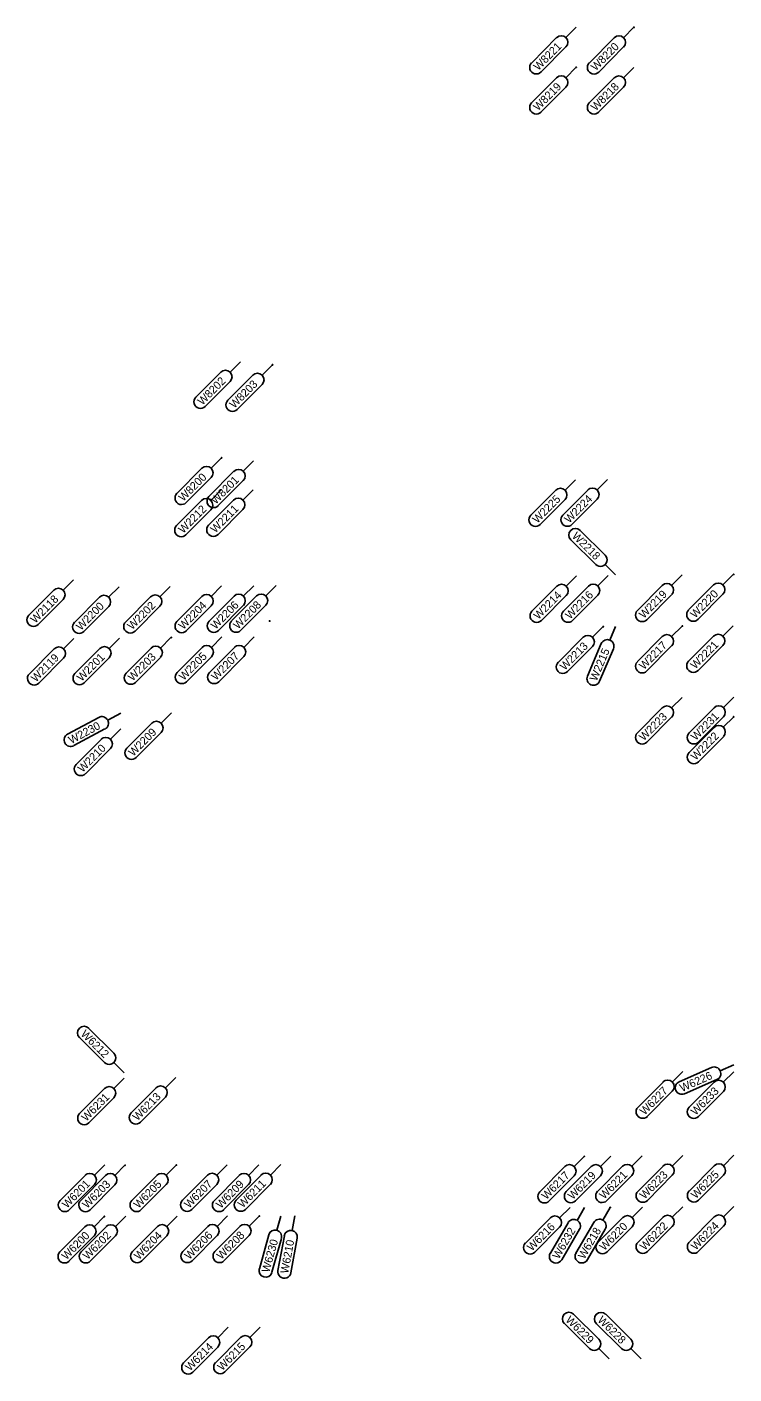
# Model space of a CAD drawing. Extents: x 12479652 to 12487250, y 9842710 to 9846560.
# Drawn here: x 12483645.7 to 12483756, y 9842728.2 to 9842938.7 of the extents above; entities that cross this region are included whole.
import ezdxf

# ---------------------------------------------------------------- set-up
doc = ezdxf.new("R2010")
doc.units = 0
doc.layers.add('_CIVIL_CONSTRUCTION', color=7, linetype='Continuous')
doc.layers.add('TextAlignmentLrg', color=7, linetype='Continuous')

msp = doc.modelspace()

# ---------------------------------------------------------------- linework, layer by layer
at = {"layer": '_CIVIL_CONSTRUCTION'}
for p, q in [((12483731.42, 9842938.62), (12483729.8, 9842936.99)), ((12483740.42, 9842938.61), (12483738.8, 9842936.98)), ((12483724.46, 9842933.07), (12483728.34, 9842936.99)), ((12483729.8, 9842935.54), (12483725.91, 9842931.63)), ((12483733.46, 9842933.06), (12483737.34, 9842936.98)), ((12483738.8, 9842935.53), (12483734.91, 9842931.62)), ((12483731.41, 9842932.36), (12483729.79, 9842930.73)), ((12483740.41, 9842932.35), (12483738.79, 9842930.72)), ((12483724.45, 9842926.81), (12483728.34, 9842930.72)), ((12483729.79, 9842929.27), (12483725.9, 9842925.36)), ((12483733.45, 9842926.8), (12483737.34, 9842930.71)), ((12483738.79, 9842929.27), (12483734.9, 9842925.35)), ((12483672.04, 9842880.81), (12483675.93, 9842884.73)), ((12483679, 9842886.36), (12483677.38, 9842884.73)), ((12483684, 9842885.88), (12483682.38, 9842884.25)), ((12483677.38, 9842883.28), (12483673.49, 9842879.37)), ((12483677.04, 9842880.34), (12483680.93, 9842884.25)), ((12483682.38, 9842882.8), (12483678.49, 9842878.89)), ((12483676.06, 9842871.35), (12483674.43, 9842869.72)), ((12483681.06, 9842870.87), (12483679.44, 9842869.24)), ((12483669.09, 9842865.8), (12483672.98, 9842869.71)), ((12483674.44, 9842868.27), (12483670.55, 9842864.35)), ((12483674.09, 9842865.32), (12483677.98, 9842869.24)), ((12483679.44, 9842867.79), (12483675.55, 9842863.88)), ((12483731.28, 9842867.92), (12483729.66, 9842866.29)), ((12483736.28, 9842867.96), (12483734.66, 9842866.33)), ((12483676.01, 9842866.33), (12483674.38, 9842864.7)), ((12483681.01, 9842866.37), (12483679.38, 9842864.74)), ((12483724.32, 9842862.37), (12483728.21, 9842866.28)), ((12483729.32, 9842862.41), (12483733.21, 9842866.32)), ((12483669.04, 9842860.78), (12483672.93, 9842864.7)), ((12483674.04, 9842860.83), (12483677.93, 9842864.74)), ((12483729.66, 9842864.84), (12483725.77, 9842860.92)), ((12483734.66, 9842864.88), (12483730.77, 9842860.97)), ((12483674.39, 9842863.25), (12483670.5, 9842859.34)), ((12483679.39, 9842863.29), (12483675.5, 9842859.38)), ((12483732, 9842860.02), (12483735.91, 9842856.13)), ((12483734.46, 9842854.67), (12483730.55, 9842858.56)), ((12483737.55, 9842853.05), (12483735.92, 9842854.68)), ((12483747.92, 9842853.06), (12483746.29, 9842851.43)), ((12483755.92, 9842853.12), (12483754.29, 9842851.49)), ((12483652.95, 9842852.31), (12483651.32, 9842850.67)), ((12483660.05, 9842851.2), (12483658.43, 9842849.57)), ((12483668.05, 9842851.27), (12483666.43, 9842849.64)), ((12483676.06, 9842851.33), (12483674.44, 9842849.7)), ((12483681.07, 9842851.37), (12483679.45, 9842849.74)), ((12483684.58, 9842851.4), (12483682.96, 9842849.77)), ((12483724.5, 9842847.37), (12483728.39, 9842851.28)), ((12483729.43, 9842847.41), (12483733.32, 9842851.32)), ((12483731.46, 9842852.92), (12483729.84, 9842851.29)), ((12483736.39, 9842852.96), (12483734.77, 9842851.33)), ((12483740.95, 9842847.51), (12483744.84, 9842851.42)), ((12483748.95, 9842847.58), (12483752.84, 9842851.49)), ((12483645.98, 9842846.76), (12483649.87, 9842850.67)), ((12483651.33, 9842849.22), (12483647.44, 9842845.31)), ((12483653.09, 9842845.65), (12483656.98, 9842849.56)), ((12483661.09, 9842845.72), (12483664.98, 9842849.63)), ((12483669.1, 9842845.78), (12483672.99, 9842849.7)), ((12483674.11, 9842845.83), (12483678, 9842849.74)), ((12483677.62, 9842845.86), (12483681.51, 9842849.77)), ((12483729.85, 9842849.84), (12483725.96, 9842845.92)), ((12483734.77, 9842849.88), (12483730.88, 9842845.97)), ((12483746.3, 9842849.97), (12483742.41, 9842846.06)), ((12483754.3, 9842850.04), (12483750.41, 9842846.13)), ((12483658.44, 9842848.12), (12483654.55, 9842844.2)), ((12483666.44, 9842848.18), (12483662.55, 9842844.27)), ((12483674.44, 9842848.25), (12483670.55, 9842844.34)), ((12483679.45, 9842848.29), (12483675.57, 9842844.38)), ((12483682.96, 9842848.32), (12483679.07, 9842844.41)), ((12483735.56, 9842844.95), (12483733.94, 9842843.32)), ((12483737.56, 9842844.98), (12483736.66, 9842842.86)), ((12483747.92, 9842845.06), (12483746.29, 9842843.43)), ((12483755.92, 9842845.12), (12483754.29, 9842843.49)), ((12483653.02, 9842843.14), (12483651.4, 9842841.51)), ((12483660.13, 9842843.2), (12483658.51, 9842841.57)), ((12483668.13, 9842843.27), (12483666.51, 9842841.64)), ((12483676.09, 9842843.37), (12483674.47, 9842841.74)), ((12483681.14, 9842843.37), (12483679.52, 9842841.74)), ((12483728.6, 9842839.4), (12483732.49, 9842843.32)), ((12483740.95, 9842839.51), (12483744.84, 9842843.42)), ((12483748.95, 9842839.58), (12483752.84, 9842843.49)), ((12483646.06, 9842837.59), (12483649.95, 9842841.51)), ((12483653.17, 9842837.65), (12483657.06, 9842841.56)), ((12483661.17, 9842837.72), (12483665.06, 9842841.63)), ((12483669.13, 9842837.82), (12483673.02, 9842841.73)), ((12483674.18, 9842837.83), (12483678.07, 9842841.74)), ((12483733.95, 9842841.87), (12483730.06, 9842837.96)), ((12483733.16, 9842837.24), (12483735.32, 9842842.32)), ((12483737.2, 9842841.52), (12483735.05, 9842836.44)), ((12483746.3, 9842841.97), (12483742.41, 9842838.06)), ((12483754.3, 9842842.04), (12483750.41, 9842838.13)), ((12483651.4, 9842840.06), (12483647.52, 9842836.15)), ((12483658.51, 9842840.12), (12483654.62, 9842836.21)), ((12483666.51, 9842840.18), (12483662.62, 9842836.27)), ((12483674.47, 9842840.28), (12483670.58, 9842836.37)), ((12483679.52, 9842840.29), (12483675.63, 9842836.38)), ((12483740.95, 9842828.39), (12483744.84, 9842832.3)), ((12483747.92, 9842833.93), (12483746.29, 9842832.3)), ((12483749.02, 9842828.4), (12483752.91, 9842832.32)), ((12483755.98, 9842833.95), (12483754.36, 9842832.32)), ((12483652.03, 9842828.19), (12483656.9, 9842830.8)), ((12483660.31, 9842831.46), (12483658.28, 9842830.38)), ((12483668.24, 9842831.52), (12483666.62, 9842829.89)), ((12483746.3, 9842830.85), (12483742.41, 9842826.94)), ((12483754.37, 9842830.87), (12483750.48, 9842826.96)), ((12483755.98, 9842830.88), (12483754.36, 9842829.25)), ((12483657.86, 9842828.99), (12483653, 9842826.39)), ((12483660.34, 9842829.01), (12483658.71, 9842827.38)), ((12483661.28, 9842825.97), (12483665.17, 9842829.88)), ((12483666.63, 9842828.44), (12483662.74, 9842824.53)), ((12483749.02, 9842825.33), (12483752.91, 9842829.24)), ((12483754.37, 9842827.79), (12483750.48, 9842823.88)), ((12483653.37, 9842823.46), (12483657.26, 9842827.37)), ((12483658.72, 9842825.92), (12483654.83, 9842822.01)), ((12483655.31, 9842782.24), (12483659.22, 9842778.35)), ((12483657.78, 9842776.89), (12483653.86, 9842780.78)), ((12483660.86, 9842775.27), (12483659.23, 9842776.9)), ((12483748.02, 9842775.48), (12483746.4, 9842773.84)), ((12483747.48, 9842773.89), (12483752.53, 9842776.11)), ((12483755.98, 9842776.51), (12483753.88, 9842775.59)), ((12483755.98, 9842775.44), (12483754.36, 9842773.81)), ((12483660.87, 9842774.46), (12483659.24, 9842772.83)), ((12483668.9, 9842774.57), (12483667.28, 9842772.94)), ((12483741.06, 9842769.93), (12483744.95, 9842773.84)), ((12483753.35, 9842774.23), (12483748.3, 9842772.01)), ((12483749.02, 9842769.89), (12483752.91, 9842773.8)), ((12483653.9, 9842768.91), (12483657.79, 9842772.82)), ((12483659.25, 9842771.38), (12483655.36, 9842767.46)), ((12483661.94, 9842769.02), (12483665.83, 9842772.94)), ((12483667.28, 9842771.49), (12483663.39, 9842767.58)), ((12483746.4, 9842772.39), (12483742.51, 9842768.48)), ((12483754.37, 9842772.36), (12483750.48, 9842768.45)), ((12483657.84, 9842760.9), (12483656.22, 9842759.27)), ((12483661.03, 9842760.88), (12483659.41, 9842759.25)), ((12483669.03, 9842760.9), (12483667.41, 9842759.27)), ((12483676.93, 9842760.92), (12483675.31, 9842759.29)), ((12483681.89, 9842760.9), (12483680.27, 9842759.26)), ((12483685.29, 9842760.94), (12483683.67, 9842759.31)), ((12483725.74, 9842756.71), (12483729.63, 9842760.62)), ((12483729.86, 9842756.73), (12483733.75, 9842760.64)), ((12483732.7, 9842762.25), (12483731.08, 9842760.62)), ((12483734.74, 9842756.76), (12483738.63, 9842760.67)), ((12483736.82, 9842762.28), (12483735.2, 9842760.65)), ((12483741.7, 9842762.31), (12483740.08, 9842760.68)), ((12483741.06, 9842756.8), (12483744.95, 9842760.71)), ((12483748.02, 9842762.35), (12483746.4, 9842760.72)), ((12483749.06, 9842756.85), (12483752.95, 9842760.76)), ((12483756.02, 9842762.4), (12483754.4, 9842760.76)), ((12483650.88, 9842755.35), (12483654.77, 9842759.26)), ((12483654.07, 9842755.33), (12483657.96, 9842759.24)), ((12483662.07, 9842755.35), (12483665.96, 9842759.26)), ((12483669.97, 9842755.37), (12483673.86, 9842759.28)), ((12483674.93, 9842755.35), (12483678.82, 9842759.26)), ((12483678.33, 9842755.39), (12483682.22, 9842759.3)), ((12483731.08, 9842759.17), (12483727.19, 9842755.26)), ((12483735.2, 9842759.2), (12483731.31, 9842755.28)), ((12483740.08, 9842759.23), (12483736.19, 9842755.31)), ((12483746.4, 9842759.27), (12483742.51, 9842755.35)), ((12483754.4, 9842759.31), (12483750.51, 9842755.4)), ((12483656.22, 9842757.82), (12483652.33, 9842753.9)), ((12483659.41, 9842757.8), (12483655.53, 9842753.88)), ((12483667.42, 9842757.82), (12483663.53, 9842753.9)), ((12483675.31, 9842757.84), (12483671.42, 9842753.92)), ((12483680.28, 9842757.81), (12483676.39, 9842753.9)), ((12483683.67, 9842757.86), (12483679.78, 9842753.94)), ((12483730.44, 9842754.24), (12483728.82, 9842752.61)), ((12483732.71, 9842754.22), (12483731.55, 9842752.23)), ((12483736.71, 9842754.24), (12483735.55, 9842752.26)), ((12483741.75, 9842754.31), (12483740.13, 9842752.68)), ((12483748.02, 9842754.35), (12483746.4, 9842752.72)), ((12483756.02, 9842754.4), (12483754.4, 9842752.76)), ((12483657.79, 9842752.87), (12483656.17, 9842751.24)), ((12483661.11, 9842752.88), (12483659.49, 9842751.25)), ((12483669.11, 9842752.9), (12483667.49, 9842751.27)), ((12483676.98, 9842752.92), (12483675.36, 9842751.29)), ((12483681.98, 9842752.93), (12483680.36, 9842751.3)), ((12483685.3, 9842752.9), (12483684.69, 9842750.69)), ((12483687.47, 9842752.91), (12483687.05, 9842750.65)), ((12483723.48, 9842748.69), (12483727.37, 9842752.61)), ((12483734.79, 9842748.76), (12483738.68, 9842752.67)), ((12483741.06, 9842748.8), (12483744.95, 9842752.71)), ((12483749.06, 9842748.85), (12483752.95, 9842752.76)), ((12483650.83, 9842747.32), (12483654.72, 9842751.23)), ((12483654.15, 9842747.33), (12483658.04, 9842751.24)), ((12483662.15, 9842747.35), (12483666.04, 9842751.26)), ((12483670.02, 9842747.37), (12483673.91, 9842751.28)), ((12483675.02, 9842747.38), (12483678.91, 9842751.29)), ((12483681.95, 9842744.66), (12483683.42, 9842749.97)), ((12483728.82, 9842751.16), (12483724.93, 9842747.25)), ((12483727.37, 9842747.1), (12483730.15, 9842751.86)), ((12483731.92, 9842750.83), (12483729.14, 9842746.07)), ((12483731.37, 9842747.12), (12483734.15, 9842751.89)), ((12483735.92, 9842750.85), (12483733.14, 9842746.09)), ((12483740.13, 9842751.23), (12483736.24, 9842747.31)), ((12483746.4, 9842751.27), (12483742.51, 9842747.35)), ((12483754.4, 9842751.31), (12483750.51, 9842747.4)), ((12483656.17, 9842749.79), (12483652.28, 9842745.88)), ((12483659.49, 9842749.8), (12483655.6, 9842745.88)), ((12483667.49, 9842749.82), (12483663.6, 9842745.9)), ((12483675.37, 9842749.84), (12483671.48, 9842745.92)), ((12483680.37, 9842749.85), (12483676.48, 9842745.94)), ((12483685.4, 9842749.42), (12483683.92, 9842744.11)), ((12483684.86, 9842744.4), (12483685.86, 9842749.82)), ((12483687.87, 9842749.45), (12483686.88, 9842744.03)), ((12483731, 9842737.56), (12483734.91, 9842733.67)), ((12483736, 9842737.55), (12483739.91, 9842733.66)), ((12483677.1, 9842735.52), (12483675.48, 9842733.88)), ((12483682.1, 9842735.55), (12483680.48, 9842733.92)), ((12483733.46, 9842732.22), (12483729.55, 9842736.11)), ((12483738.46, 9842732.2), (12483734.55, 9842736.09)), ((12483670.14, 9842729.97), (12483674.03, 9842733.88)), ((12483675.14, 9842730), (12483679.03, 9842733.91)), ((12483675.48, 9842732.43), (12483671.59, 9842728.52)), ((12483680.48, 9842732.47), (12483676.59, 9842728.55)), ((12483736.55, 9842730.6), (12483734.92, 9842732.22)), ((12483741.55, 9842730.59), (12483739.92, 9842732.21))]:
    msp.add_line(p, q, dxfattribs=at)
for centre, start, end in [((12483729.07, 9842936.26), 315.1702, 135.1702), ((12483738.07, 9842936.25), 315.1702, 135.1702), ((12483725.18, 9842932.35), 135.1702, 315.1702), ((12483734.18, 9842932.34), 135.1702, 315.1702), ((12483729.07, 9842930), 315.1702, 135.1702), ((12483738.07, 9842929.99), 315.1702, 135.1702), ((12483725.18, 9842926.08), 135.1702, 315.1702), ((12483734.18, 9842926.08), 135.1702, 315.1702), ((12483676.66, 9842884), 315.1702, 135.1702), ((12483681.66, 9842883.53), 315.1702, 135.1702), ((12483672.77, 9842880.09), 135.1702, 315.1702), ((12483677.77, 9842879.61), 135.1702, 315.1702), ((12483673.71, 9842868.99), 315.1702, 135.1702), ((12483678.71, 9842868.51), 315.1702, 135.1702), ((12483669.82, 9842865.08), 135.1702, 315.1702), ((12483728.93, 9842865.56), 315.1702, 135.1702), ((12483733.93, 9842865.6), 315.1702, 135.1702), ((12483673.66, 9842863.97), 315.1702, 135.1702), ((12483674.82, 9842864.6), 135.1702, 315.1702), ((12483678.66, 9842864.02), 315.1702, 135.1702), ((12483725.04, 9842861.65), 135.1702, 315.1702), ((12483730.04, 9842861.69), 135.1702, 315.1702), ((12483669.77, 9842860.06), 135.1702, 315.1702), ((12483674.77, 9842860.1), 135.1702, 315.1702), ((12483731.27, 9842859.29), 45.1702, 225.1702), ((12483735.19, 9842855.4), 225.1702, 45.1702), ((12483650.6, 9842849.95), 315.1702, 135.1702), ((12483729.12, 9842850.56), 315.1702, 135.1702), ((12483734.05, 9842850.6), 315.1702, 135.1702), ((12483745.57, 9842850.7), 315.1702, 135.1702), ((12483753.57, 9842850.76), 315.1702, 135.1702), ((12483657.71, 9842848.84), 315.1702, 135.1702), ((12483665.71, 9842848.91), 315.1702, 135.1702), ((12483673.72, 9842848.97), 315.1702, 135.1702), ((12483678.73, 9842849.02), 315.1702, 135.1702), ((12483682.24, 9842849.04), 315.1702, 135.1702), ((12483646.71, 9842846.03), 135.1702, 315.1702), ((12483725.23, 9842846.65), 135.1702, 315.1702), ((12483730.16, 9842846.69), 135.1702, 315.1702), ((12483741.68, 9842846.79), 135.1702, 315.1702), ((12483749.68, 9842846.85), 135.1702, 315.1702), ((12483653.82, 9842844.93), 135.1702, 315.1702), ((12483661.82, 9842844.99), 135.1702, 315.1702), ((12483669.83, 9842845.06), 135.1702, 315.1702), ((12483674.84, 9842845.1), 135.1702, 315.1702), ((12483678.35, 9842845.13), 135.1702, 315.1702), ((12483733.22, 9842842.59), 315.1702, 135.1702), ((12483736.26, 9842841.92), 336.962, 156.962), ((12483745.57, 9842842.7), 315.1702, 135.1702), ((12483753.57, 9842842.76), 315.1702, 135.1702), ((12483650.68, 9842840.78), 315.1702, 135.1702), ((12483657.79, 9842840.84), 315.1702, 135.1702), ((12483665.79, 9842840.91), 315.1702, 135.1702), ((12483673.75, 9842841.01), 315.1702, 135.1702), ((12483678.79, 9842841.02), 315.1702, 135.1702), ((12483729.33, 9842838.68), 135.1702, 315.1702), ((12483741.68, 9842838.78), 135.1702, 315.1702), ((12483749.68, 9842838.85), 135.1702, 315.1702), ((12483646.79, 9842836.87), 135.1702, 315.1702), ((12483653.9, 9842836.93), 135.1702, 315.1702), ((12483661.9, 9842837), 135.1702, 315.1702), ((12483669.86, 9842837.1), 135.1702, 315.1702), ((12483674.9, 9842837.1), 135.1702, 315.1702), ((12483734.1, 9842836.84), 156.962, 336.962), ((12483745.57, 9842831.57), 315.1702, 135.1702), ((12483753.64, 9842831.59), 315.1702, 135.1702), ((12483657.38, 9842829.89), 298.1338, 118.1338), ((12483665.9, 9842829.16), 315.1702, 135.1702), ((12483652.51, 9842827.29), 118.1338, 298.1338), ((12483741.68, 9842827.66), 135.1702, 315.1702), ((12483749.75, 9842827.68), 135.1702, 315.1702), ((12483753.64, 9842828.52), 315.1702, 135.1702), ((12483657.99, 9842826.65), 315.1702, 135.1702), ((12483662.01, 9842825.25), 135.1702, 315.1702), ((12483749.75, 9842824.6), 135.1702, 315.1702), ((12483654.1, 9842822.74), 135.1702, 315.1702), ((12483654.59, 9842781.51), 45.1702, 225.1702), ((12483658.5, 9842777.62), 225.1702, 45.1702), ((12483752.94, 9842775.17), 293.7594, 113.7594), ((12483658.52, 9842772.1), 315.1702, 135.1702), ((12483666.55, 9842772.21), 315.1702, 135.1702), ((12483745.67, 9842773.12), 315.1702, 135.1702), ((12483747.89, 9842772.95), 113.7594, 293.7594), ((12483753.64, 9842773.08), 315.1702, 135.1702), ((12483654.63, 9842768.19), 135.1702, 315.1702), ((12483662.67, 9842768.3), 135.1702, 315.1702), ((12483741.78, 9842769.2), 135.1702, 315.1702), ((12483749.75, 9842769.17), 135.1702, 315.1702), ((12483730.35, 9842759.9), 315.1702, 135.1702), ((12483734.47, 9842759.92), 315.1702, 135.1702), ((12483739.36, 9842759.95), 315.1702, 135.1702), ((12483745.67, 9842759.99), 315.1702, 135.1702), ((12483753.67, 9842760.04), 315.1702, 135.1702), ((12483655.49, 9842758.54), 315.1702, 135.1702), ((12483658.69, 9842758.52), 315.1702, 135.1702), ((12483666.69, 9842758.54), 315.1702, 135.1702), ((12483674.58, 9842758.56), 315.1702, 135.1702), ((12483679.55, 9842758.54), 315.1702, 135.1702), ((12483682.94, 9842758.58), 315.1702, 135.1702), ((12483726.46, 9842755.98), 135.1702, 315.1702), ((12483730.58, 9842756.01), 135.1702, 315.1702), ((12483735.47, 9842756.04), 135.1702, 315.1702), ((12483741.78, 9842756.08), 135.1702, 315.1702), ((12483749.78, 9842756.12), 135.1702, 315.1702), ((12483651.6, 9842754.63), 135.1702, 315.1702), ((12483654.8, 9842754.61), 135.1702, 315.1702), ((12483662.8, 9842754.63), 135.1702, 315.1702), ((12483670.7, 9842754.65), 135.1702, 315.1702), ((12483675.66, 9842754.62), 135.1702, 315.1702), ((12483679.05, 9842754.67), 135.1702, 315.1702), ((12483728.09, 9842751.88), 315.1702, 135.1702), ((12483731.03, 9842751.35), 329.7181, 149.7181), ((12483735.04, 9842751.37), 329.7181, 149.7181), ((12483739.41, 9842751.95), 315.1702, 135.1702), ((12483745.67, 9842751.99), 315.1702, 135.1702), ((12483753.67, 9842752.04), 315.1702, 135.1702), ((12483655.45, 9842750.51), 315.1702, 135.1702), ((12483658.76, 9842750.52), 315.1702, 135.1702), ((12483666.77, 9842750.54), 315.1702, 135.1702), ((12483674.64, 9842750.56), 315.1702, 135.1702), ((12483679.64, 9842750.57), 315.1702, 135.1702), ((12483684.41, 9842749.7), 344.4632, 164.4632), ((12483686.86, 9842749.64), 349.5897, 169.5897), ((12483724.2, 9842747.97), 135.1702, 315.1702), ((12483735.52, 9842748.04), 135.1702, 315.1702), ((12483741.78, 9842748.08), 135.1702, 315.1702), ((12483749.78, 9842748.12), 135.1702, 315.1702), ((12483651.56, 9842746.6), 135.1702, 315.1702), ((12483654.88, 9842746.61), 135.1702, 315.1702), ((12483662.88, 9842746.63), 135.1702, 315.1702), ((12483670.75, 9842746.65), 135.1702, 315.1702), ((12483675.75, 9842746.66), 135.1702, 315.1702), ((12483728.25, 9842746.58), 149.7181, 329.7181), ((12483732.26, 9842746.61), 149.7181, 329.7181), ((12483682.93, 9842744.38), 164.4632, 344.4632), ((12483685.87, 9842744.21), 169.5897, 349.5897), ((12483730.27, 9842736.84), 45.1702, 225.1702), ((12483735.27, 9842736.82), 45.1702, 225.1702), ((12483674.75, 9842733.16), 315.1702, 135.1702), ((12483679.75, 9842733.19), 315.1702, 135.1702), ((12483734.19, 9842732.95), 225.1702, 45.1702), ((12483739.19, 9842732.93), 225.1702, 45.1702), ((12483670.86, 9842729.24), 135.1702, 315.1702), ((12483675.86, 9842729.28), 135.1702, 315.1702)]:
    msp.add_arc(centre, 1.03, start, end, dxfattribs=at)
at = {"layer": 'TextAlignmentLrg'}
for centre in [(12483740.42, 9842938.61), (12483731.41, 9842932.36), (12483684, 9842885.88), (12483676.06, 9842871.35), (12483755.98, 9842853.14), (12483683.57, 9842845.85), (12483735.63, 9842844.97), (12483747.98, 9842845.07), (12483668.2, 9842843.28), (12483755.98, 9842830.88), (12483661, 9842760.84), (12483669, 9842760.86), (12483732.66, 9842762.22), (12483736.71, 9842754.24), (12483657.76, 9842752.84), (12483681.95, 9842752.9)]:
    msp.add_circle(centre, 0.05, dxfattribs=at)

# ---------------------------------------------------------------- texts
at = {"layer": '_CIVIL_CONSTRUCTION'}
for s, rotation, p in [('W8221', 45.1702, (12483725.49, 9842931.76)), ('W8220', 45.1702, (12483734.45, 9842931.71)), ('W8219', 45.1702, (12483725.45, 9842925.46)), ('W8218', 45.1702, (12483734.45, 9842925.45)), ('W8202', 45.1702, (12483673.06, 9842879.48)), ('W8203', 45.1702, (12483678.05, 9842878.99)), ('W8200', 45.1702, (12483670.09, 9842864.45)), ('W8201', 45.1702, (12483675.13, 9842864.01)), ('W2212', 45.1702, (12483670.06, 9842859.45)), ('W2211', 45.1702, (12483675.08, 9842859.51)), ('W2225', 45.1702, (12483725.33, 9842861.03)), ('W2224', 45.1702, (12483730.31, 9842861.05)), ('W2218', 315.1702, (12483730.65, 9842859.02)), ('W2118', 45.1702, (12483646.98, 9842845.41)), ('W2202', 45.1702, (12483662.11, 9842844.39)), ('W2204', 45.1702, (12483670.09, 9842844.43)), ('W2206', 45.1702, (12483675.11, 9842844.47)), ('W2208', 45.1702, (12483678.62, 9842844.5)), ('W2214', 45.1702, (12483725.49, 9842846.01)), ('W2216', 45.1702, (12483730.43, 9842846.06)), ('W2219', 45.1702, (12483741.95, 9842846.16)), ('W2220', 45.1702, (12483749.95, 9842846.22)), ('W2200', 45.1702, (12483654.09, 9842844.3)), ('W2217', 45.1702, (12483741.96, 9842838.17)), ('W2221', 45.1702, (12483749.99, 9842838.26)), ('W2119', 45.1702, (12483647.06, 9842836.24)), ('W2201', 45.1702, (12483654.2, 9842836.34)), ('W2203', 45.1702, (12483662.18, 9842836.38)), ('W2205', 45.1702, (12483670.14, 9842836.48)), ('W2207', 45.1702, (12483675.19, 9842836.49)), ('W2213', 45.1702, (12483729.61, 9842838.06)), ('W2215', 66.962, (12483734.59, 9842836.37)), ('W2230', 28.1338, (12483652.59, 9842826.61)), ('W2223', 45.1702, (12483741.96, 9842827.04)), ('W2231', 45.1702, (12483750.06, 9842827.09)), ('W2209', 45.1702, (12483662.28, 9842824.62)), ('W2222', 45.1702, (12483750.04, 9842824)), ('W2210', 45.1702, (12483654.37, 9842822.11)), ('W6212', 315.1702, (12483653.98, 9842781.22)), ('W6226', 23.7594, (12483747.91, 9842772.26)), ('W6227', 45.1702, (12483742.07, 9842768.59)), ('W6231', 45.1702, (12483654.94, 9842767.6)), ('W6213', 45.1702, (12483662.94, 9842767.68)), ('W6233', 45.1702, (12483750.03, 9842768.55)), ('W6201', 45.1702, (12483651.91, 9842754.03)), ('W6203', 45.1702, (12483655.08, 9842753.99)), ('W6205', 45.1702, (12483663.08, 9842754.01)), ('W6207', 45.1702, (12483670.98, 9842754.03)), ('W6209', 45.1702, (12483675.93, 9842754)), ('W6211', 45.1702, (12483679.36, 9842754.08)), ('W6217', 45.1702, (12483726.75, 9842755.37)), ('W6219', 45.1702, (12483730.86, 9842755.38)), ('W6221', 45.1702, (12483735.77, 9842755.45)), ('W6223', 45.1702, (12483742.06, 9842755.46)), ('W6225', 45.1702, (12483750.07, 9842755.51)), ('W6200', 45.1702, (12483651.83, 9842745.97)), ('W6202', 45.1702, (12483655.17, 9842746)), ('W6204', 45.1702, (12483663.14, 9842745.99)), ('W6206', 45.1702, (12483671.02, 9842746.02)), ('W6208', 45.1702, (12483676.02, 9842746.03)), ('W6216', 45.1702, (12483724.47, 9842747.34)), ('W6232', 59.7181, (12483728.69, 9842746.07)), ('W6218', 59.7181, (12483732.68, 9842746.07)), ('W6220', 45.1702, (12483735.79, 9842747.41)), ('W6222', 45.1702, (12483742.08, 9842747.47)), ('W6224', 45.1702, (12483750.05, 9842747.49)), ('W6230', 74.4632, (12483683.48, 9842743.97)), ('W6210', 79.5897, (12483686.45, 9842743.85)), ('W6229', 315.1702, (12483729.65, 9842736.56)), ('W6228', 315.1702, (12483734.65, 9842736.55)), ('W6214', 45.1702, (12483671.13, 9842728.61)), ('W6215', 45.1702, (12483676.15, 9842728.66))]:
    msp.add_text(s, height=1.25, rotation=rotation, dxfattribs=at).set_placement(p)

doc.saveas('drawing.dxf')
